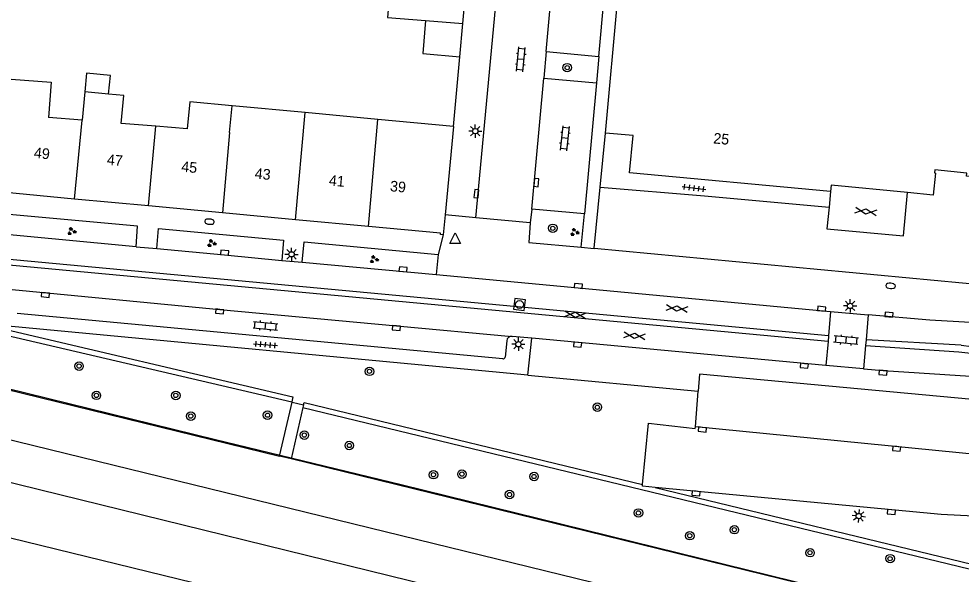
# Model space of a CAD drawing. Extents: x 132998 to 136004, y 396998 to 398512.
# Drawn here: x 133137.8 to 133226.6, y 397038.8 to 397091.2 of the extents above; entities that cross this region are included whole.
import ezdxf

# ---------------------------------------------------------------- set-up
doc = ezdxf.new("R2010")
doc.units = 0
for name, color, linetype in [('gg-afsc-muur', 7, 'Continuous'), ('gg-anno-huisnummerreeks BGT', 7, 'Continuous'), ('gg-aspt-spoorlijn', 7, 'Continuous'), ('gg-bbg-bijgebouw', 7, 'Continuous'), ('gg-bbg-gedigitaliseerde bebouwing', 7, 'Continuous'), ('gg-bbg-gedigitaliseerde bijgebouw', 7, 'Continuous'), ('gg-bbg-hoofdgebouw', 7, 'Continuous'), ('gg-bbg-luifel en loopbrug', 7, 'Continuous'), ('gg-bbg-tussenscheiding', 7, 'Continuous'), ('gg-knt-trap', 7, 'Continuous'), ('gg-knt-verharding', 7, 'Continuous'), ('gg-knt-verharding nz', 7, 'Continuous'), ('gg-kntw-beschoeiing', 7, 'Continuous'), ('gt-grn-groengrens', 7, 'Continuous'), ('gt-grn-weggrens', 7, 'Continuous'), ('gt-symb-boom', 7, 'Continuous'), ('gt-symb-brandkraan', 7, 'Continuous'), ('gt-symb-gesloten verharding', 7, 'Continuous'), ('gt-symb-groenvak', 7, 'Continuous'), ('gt-symb-klinker verharding', 7, 'Continuous'), ('gt-symb-kolk', 7, 'Continuous'), ('gt-symb-lichtmast', 7, 'Continuous'), ('gt-symb-rioolschacht', 7, 'Continuous'), ('gt-symb-tegel verharding', 7, 'Continuous'), ('gt-symb-waterafsluiter', 7, 'Continuous'), ('gx-grn-maaiveld', 7, 'Continuous')]:
    doc.layers.add(name, color=color, linetype=linetype)

# ---------------------------------------------------------------- blocks, each defined once
blk = doc.blocks.new('gt0-KOLK')
at = {"layer": 'gt-symb-kolk'}
blk.add_lwpolyline([(0, 0), (0.375, 0), (0.375, 0.4), (-0.375, 0.4), (-0.375, 0), (0, 0)], dxfattribs=at)
blk = doc.blocks.new('gt0-GESVH1')
at = {"layer": 'gt-symb-gesloten verharding'}
for p, q in [((-0.992, -0.261), (0.008, 0.239)), ((0.008, -0.261), (-0.992, 0.239)), ((0.008, 0.239), (1.008, -0.261)), ((1.008, 0.239), (0.008, -0.261))]:
    blk.add_line(p, q, dxfattribs=at)
blk = doc.blocks.new('gt0-BR')
at = {"layer": 'gt-symb-brandkraan'}
for centre, radius, start, end in [((-0.244, 0), 0.206, 107.56694, 252.43307), ((0.599, -2.664), 3, 106.89205, 107.56694), ((0, -0.691), 0.938, 73.10799, 106.89205), ((-0.599, -2.664), 3, 72.43309, 73.10799), ((0.244, 0), 0.206, 287.56695, 72.43309), ((0.599, 2.664), 3, 252.43307, 253.10797), ((0, 0.691), 0.938, 253.10797, 286.89206), ((-0.599, 2.664), 3, 286.89206, 287.56695)]:
    blk.add_arc(centre, radius, start, end, dxfattribs=at)
blk = doc.blocks.new('gt0-KL1')
at = {"layer": 'gt-symb-klinker verharding'}
for p, q in [((-1.15, 0.3), (1.15, 0.3)), ((-1, -0.3), (-1, 0.3)), ((-0.5, 0.3), (-0.5, 0.45)), ((0, -0.3), (0, 0.3)), ((0.5, 0.3), (0.5, 0.45)), ((1, -0.3), (1, 0.3)), ((-1.15, -0.3), (1.15, -0.3)), ((-0.5, -0.45), (-0.5, -0.3)), ((0.5, -0.45), (0.5, -0.3))]:
    blk.add_line(p, q, dxfattribs=at)
blk = doc.blocks.new('gt0-LMAST')
at = {"layer": 'gt-symb-lichtmast'}
for p, q in [((-0.182, 0.173), (-0.447, 0.438)), ((-0.005, 0.246), (-0.005, 0.621)), ((0.172, 0.173), (0.437, 0.438)), ((-0.255, -0.004), (-0.63, -0.004)), ((-0.182, -0.181), (-0.447, -0.446)), ((-0.005, -0.254), (-0.005, -0.629)), ((0.437, -0.446), (0.172, -0.181)), ((0.245, -0.004), (0.62, -0.004))]:
    blk.add_line(p, q, dxfattribs=at)
blk.add_circle((-0.005, -0.004), 0.25, dxfattribs=at)
blk = doc.blocks.new('gt0-WAFSL')
at = {"layer": 'gt-symb-waterafsluiter'}
for p, q in [((-0.5, -0.333), (0, 0.667)), ((0, 0.667), (0.5, -0.333)), ((0.5, -0.333), (-0.5, -0.333))]:
    blk.add_line(p, q, dxfattribs=at)
blk = doc.blocks.new('gt0-BOOM')
at = {"layer": 'gt-symb-boom'}
for radius in [0.4, 0.2]:
    blk.add_circle((0, 0), radius, dxfattribs=at)
blk = doc.blocks.new('gt0-GRVAK')
at = {"layer": 'gt-symb-groenvak'}
for p, q in [((-0.11, 0.189), (-0.228, 0.24)), ((-0.182, 0.153), (0.088, 0.153)), ((-0.091, 0.211), (-0.156, 0.322)), ((-0.047, 0.214), (-0.047, 0.393)), ((-0.004, 0.211), (0.061, 0.322)), ((0.015, 0.189), (0.133, 0.24)), ((0.262, -0.052), (0.197, 0.059)), ((0.305, -0.049), (0.305, 0.13)), ((0.349, -0.052), (0.414, 0.059)), ((-0.245, -0.228), (-0.363, -0.177)), ((-0.318, -0.264), (-0.047, -0.264)), ((-0.226, -0.206), (-0.291, -0.095)), ((-0.183, -0.203), (-0.183, -0.024)), ((-0.139, -0.206), (-0.074, -0.095)), ((-0.12, -0.228), (-0.002, -0.177)), ((0.243, -0.074), (0.125, -0.023)), ((0.17, -0.11), (0.441, -0.11)), ((0.368, -0.074), (0.486, -0.023))]:
    blk.add_line(p, q, dxfattribs=at)
blk = doc.blocks.new('gt0-TEG1')
at = {"layer": 'gt-symb-tegel verharding'}
for p, q in [((-1.125, 0), (1.125, 0)), ((-0.9, -0.25), (-0.9, 0.25)), ((-0.45, -0.25), (-0.45, 0.25)), ((0, -0.25), (0, 0.25)), ((0.45, -0.25), (0.45, 0.25)), ((0.9, -0.25), (0.9, 0.25))]:
    blk.add_line(p, q, dxfattribs=at)
blk = doc.blocks.new('gt0-RS')
at = {"layer": 'gt-symb-rioolschacht'}
blk.add_lwpolyline([(-0.5, -0.5), (0.5, -0.5), (0.5, 0.5), (-0.5, 0.5)], close=True, dxfattribs=at)
blk.add_circle((0, 0), 0.375, dxfattribs=at)

msp = doc.modelspace()

# ---------------------------------------------------------------- linework, layer by layer
at = {"layer": 'gg-afsc-muur'}
for p, q in [((133178.77, 397081), (133179.359, 397087.567)), ((133163.478, 397049.706), (133162.377, 397049.975)), ((133163.478, 397049.706), (133162.377, 397049.975)), ((133293.74, 397017.818), (133163.478, 397049.706)), ((133293.74, 397017.818), (133163.478, 397049.706))]:
    msp.add_line(p, q, dxfattribs=at)
at = {"layer": 'gg-aspt-spoorlijn'}
msp.add_line((133000, 397081.027), (133298.474, 397007.929), dxfattribs=at)
for points in [[(133000, 397085.097), (133023.788, 397079.291), (133131.609, 397052.829), (133298.931, 397011.894)], [(133000, 397075.839), (133096.746, 397052.101), (133297.901, 397002.954)]]:
    msp.add_lwpolyline(points, dxfattribs=at)
at = {"layer": 'gg-bbg-bijgebouw'}
msp.add_line((133179.643, 397090.725), (133179.919, 397093.721), dxfattribs=at)
at = {"layer": 'gg-bbg-gedigitaliseerde bebouwing'}
for p, q in [((133140.841, 397085.19), (133140.575, 397081.876)), ((133144.011, 397084.267), (133143.763, 397081.611)), ((133146.252, 397084.058), (133144.011, 397084.267)), ((133164.779, 397082.32), (133157.896, 397082.97)), ((133171.649, 397081.672), (133164.779, 397082.32)), ((133143.763, 397081.611), (133140.575, 397081.876)), ((133150.698, 397081.034), (133147.45, 397081.304)), ((133178.77, 397081), (133171.649, 397081.672)), ((133153.675, 397080.786), (133150.698, 397081.034))]:
    msp.add_line(p, q, dxfattribs=at)
for points in [[(133147.45, 397081.304), (133147.695, 397083.923), (133146.252, 397084.058)], [(133157.896, 397082.97), (133153.913, 397083.342), (133153.675, 397080.786)]]:
    msp.add_lwpolyline(points, dxfattribs=at)
at = {"layer": 'gg-bbg-gedigitaliseerde bijgebouw'}
msp.add_line((133176.146, 397091.006), (133179.643, 397090.725), dxfattribs=at)
msp.add_lwpolyline([(133172.805, 397094.266), (133172.549, 397091.296), (133176.146, 397091.006)], dxfattribs=at)
at = {"layer": 'gg-bbg-hoofdgebouw'}
for p, q in [((133193.09, 397080.4), (133194.795, 397098.793)), ((133137.08, 397085.49), (133140.841, 397085.19)), ((133178.77, 397081), (133177.98, 397072.698)), ((133143.043, 397074.185), (133136.251, 397074.82)), ((133150.023, 397073.533), (133143.043, 397074.185)), ((133156.983, 397072.883), (133150.023, 397073.533)), ((133163.879, 397072.238), (133156.983, 397072.883)), ((133177.98, 397072.698), (133177.8, 397070.81)), ((133170.751, 397071.596), (133163.879, 397072.238))]:
    msp.add_line(p, q, dxfattribs=at)
for points in [[(133214.33, 397074.88), (133195.38, 397076.64), (133195.7, 397080.16), (133193.09, 397080.4)], [(133233.58, 397075.72), (133227.141, 397076.348), (133227.168, 397076.627), (133224.148, 397076.921), (133224.121, 397076.642), (133224.211, 397076.633), (133224.009, 397074.56), (133221.575, 397074.797)], [(133221.575, 397074.797), (133214.39, 397075.498), (133214.33, 397074.88)], [(133177.8, 397070.81), (133177.54, 397070.85), (133177.56, 397070.96), (133170.751, 397071.596)]]:
    msp.add_lwpolyline(points, dxfattribs=at)
at = {"layer": 'gg-bbg-luifel en loopbrug'}
msp.add_line((133179.359, 397087.567), (133179.643, 397090.725), dxfattribs=at)
for points in [[(133176.146, 397091.006), (133175.865, 397087.88), (133179.359, 397087.567)], [(133146.252, 397084.058), (133146.418, 397085.833), (133144.177, 397086.042), (133144.011, 397084.267)]]:
    msp.add_lwpolyline(points, dxfattribs=at)
at = {"layer": 'gg-bbg-tussenscheiding'}
for p, q in [((133157.668, 397080.454), (133157.896, 397082.97)), ((133163.879, 397072.238), (133164.779, 397082.32)), ((133143.043, 397074.185), (133143.763, 397081.611)), ((133170.751, 397071.596), (133171.649, 397081.672)), ((133150.023, 397073.533), (133150.698, 397081.034)), ((133157.668, 397080.454), (133156.983, 397072.883))]:
    msp.add_line(p, q, dxfattribs=at)
at = {"layer": 'gg-knt-trap'}
for p, q in [((133214.33, 397074.88), (133214.181, 397073.41)), ((133162.377, 397049.975), (133163.477, 397054.631)), ((133163.477, 397054.631), (133163.574, 397055.041)), ((133163.574, 397055.041), (133164.628, 397054.78)), ((133164.628, 397054.78), (133164.573, 397054.536)), ((133164.573, 397054.536), (133163.478, 397049.706))]:
    msp.add_line(p, q, dxfattribs=at)
msp.add_lwpolyline([(133214.181, 397073.41), (133213.976, 397071.385), (133221.205, 397070.728), (133221.575, 397074.797)], dxfattribs=at)
at = {"layer": 'gg-knt-verharding'}
for p, q in [((133180.888, 397072.421), (133183.8, 397103.83)), ((133192.487, 397087.621), (133193.481, 397098.903)), ((133187.51, 397088.071), (133187.277, 397085.582)), ((133187.51, 397088.071), (133192.487, 397087.621)), ((133187.277, 397085.582), (133192.239, 397085.131)), ((133192.239, 397085.131), (133191.113, 397072.778)), ((133192.596, 397075.291), (133193.09, 397080.4)), ((133192.043, 397069.557), (133192.596, 397075.291)), ((133192.596, 397075.291), (133202.43, 397074.478)), ((133202.43, 397074.478), (133214.181, 397073.41)), ((133186.011, 397071.946), (133180.888, 397072.421)), ((133186.149, 397073.231), (133186.011, 397071.946)), ((133191.113, 397072.778), (133186.149, 397073.231)), ((133148.859, 397069.679), (133150.804, 397069.51)), ((133177.317, 397068.957), (133177.134, 397067.06)), ((133162.572, 397068.403), (133164.507, 397068.233)), ((133164.507, 397068.233), (133177.134, 397067.06)), ((133177.134, 397067.06), (133214.326, 397063.573)), ((133214.326, 397063.573), (133214.126, 397061.302)), ((133214.326, 397063.573), (133217.868, 397063.267)), ((133183.413, 397059.125), (133137.626, 397063.393)), ((133217.868, 397063.267), (133217.667, 397060.921)), ((133185.776, 397057.595), (133134.977, 397062.367)), ((133183.785, 397060.823), (133183.627, 397059.297)), ((133186.148, 397061.069), (133184.287, 397061.244)), ((133185.776, 397057.595), (133186.148, 397061.069)), ((133213.879, 397058.486), (133186.148, 397061.069)), ((133214.126, 397061.302), (133214.08, 397060.772)), ((133217.667, 397060.921), (133217.622, 397060.394)), ((133226.633, 397060.413), (133217.667, 397060.921)), ((133214.08, 397060.772), (133213.879, 397058.486)), ((133217.622, 397060.394), (133217.432, 397058.174)), ((133217.622, 397060.394), (133226.414, 397059.782)), ((133217.432, 397058.174), (133213.879, 397058.486)), ((133217.432, 397058.174), (133219.287, 397058.019)), ((133219.287, 397058.019), (133228.484, 397057.43)), ((133201.58, 397052.738), (133201.842, 397056.086))]:
    msp.add_line(p, q, dxfattribs=at)
for points in [[(133148.859, 397069.679), (133148.993, 397071.615), (133136.203, 397072.795)], [(133186.011, 397071.946), (133185.863, 397070.102), (133190.823, 397069.643)], [(133148.859, 397069.679), (133137.248, 397070.793), (133136.073, 397070.882)], [(133150.804, 397069.51), (133150.955, 397071.42), (133162.749, 397070.311), (133162.572, 397068.403)], [(133164.507, 397068.233), (133164.699, 397070.145), (133177.317, 397068.957)], [(133192.043, 397069.557), (133232.1, 397065.79), (133242.55, 397070.43)], [(133150.804, 397069.51), (133157.185, 397068.93), (133162.572, 397068.403)], [(133190.823, 397069.643), (133192.04, 397069.531), (133192.043, 397069.557)], [(133214.08, 397060.772), (133136.179, 397068.014), (133135.632, 397068.061)], [(133214.126, 397061.302), (133136.243, 397068.553), (133135.715, 397068.593)], [(133137.156, 397065.651), (133156.738, 397063.791), (133173.408, 397062.236), (133184.287, 397061.244)], [(133229.16, 397062.468), (133223.69, 397062.769), (133217.868, 397063.267)], [(133237.59, 397055.191), (133237.36, 397055.09), (133230.74, 397055), (133201.968, 397057.692), (133201.842, 397056.086)], [(133196.606, 397047.301), (133197.16, 397053.07), (133201.567, 397052.566), (133201.58, 397052.738)], [(133197.779, 397047.017), (133196.59, 397047.13), (133196.606, 397047.301)], [(133231.483, 397044.133), (133224.75, 397044.46), (133197.779, 397047.017)]]:
    msp.add_lwpolyline(points, dxfattribs=at)
for centre, radius, start, end in [((133230.067, 397085.427), 25.249, 262.18313, 297.37096), ((133184.25, 397060.779), 0.467, 85.42767, 174.54178), ((133229.546, 397086.551), 26.951, 263.32581, 292.38921), ((133183.411, 397059.347), 0.222, 270.62746, 346.95289)]:
    msp.add_arc(centre, radius, start, end, dxfattribs=at)
at = {"layer": 'gg-knt-verharding nz'}
for p, q in [((133186.149, 397073.231), (133187.277, 397085.582)), ((133230.616, 397049.869), (133201.58, 397052.738))]:
    msp.add_line(p, q, dxfattribs=at)
msp.add_lwpolyline([(133187.51, 397088.071), (133187.881, 397092.238), (133188.132, 397094.871), (133188.621, 397100.501)], dxfattribs=at)
at = {"layer": 'gg-kntw-beschoeiing'}
msp.add_lwpolyline([(133293.908, 397017.321), (133294.015, 397017.844), (133281.102, 397020.96), (133261.323, 397025.845), (133257.889, 397026.669), (133240.574, 397030.918), (133215.176, 397037.087), (133173.826, 397047.249), (133156.339, 397051.485), (133065.484, 397073.822), (133055.258, 397076.278), (133002.984, 397089.089), (133000, 397089.82)], dxfattribs=at)
at = {"layer": 'gt-grn-groengrens'}
for p, q in [((133192.487, 397087.621), (133192.239, 397085.131)), ((133190.823, 397069.643), (133191.113, 397072.778)), ((133185.776, 397057.595), (133201.842, 397056.086)), ((133163.517, 397055.064), (133163.574, 397055.041)), ((133197.779, 397047.017), (133231.465, 397038.868))]:
    msp.add_line(p, q, dxfattribs=at)
for points in [[(133041.069, 397084.222), (133093.229, 397072.243), (133093.148, 397070.541), (133113.163, 397066.046), (133113.393, 397066.97), (133134.695, 397061.803), (133163.517, 397055.064)], [(133134.951, 397062.257), (133163.631, 397055.55), (133163.517, 397055.064)], [(133164.628, 397054.78), (133164.687, 397055.023), (133196.606, 397047.301)], [(133164.573, 397054.536), (133272.285, 397028.478), (133272.447, 397029.147)]]:
    msp.add_lwpolyline(points, dxfattribs=at)
at = {"layer": 'gt-grn-weggrens'}
for p, q in [((133180.888, 397072.421), (133177.98, 397072.698)), ((133177.8, 397070.81), (133177.317, 397068.957))]:
    msp.add_line(p, q, dxfattribs=at)
at = {"layer": 'gx-grn-maaiveld'}
msp.add_lwpolyline([(133004.183, 397088.7), (133026.835, 397083.155), (133162.377, 397049.975)], dxfattribs=at)

# ---------------------------------------------------------------- block references
at = {"layer": 'gt-symb-boom'}
for p in [(133189.489, 397086.558), (133188.133, 397071.424), (133143.471, 397058.443), (133170.848, 397057.95), (133145.105, 397055.686), (133152.592, 397055.679), (133192.333, 397054.57), (133154.001, 397053.734), (133161.237, 397053.819), (133164.709, 397051.945), (133168.948, 397050.964), (133176.883, 397048.21), (133179.568, 397048.27), (133186.363, 397048.041), (133184.055, 397046.342), (133196.208, 397044.612), (133205.25, 397043.031), (133201.048, 397042.464), (133212.386, 397040.867), (133219.934, 397040.307)]:
    msp.add_blockref('gt0-BOOM', p, dxfattribs=at)
at = {"layer": 'gt-symb-brandkraan'}
for p, rotation in [((133155.763, 397072.051), 174.3179150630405), ((133219.982, 397066.002), 176.0449623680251)]:
    msp.add_blockref('gt0-BR', p, dxfattribs=dict(at, rotation=rotation))
at = {"layer": 'gt-symb-gesloten verharding'}
for p, rotation in [((133217.641, 397073.027), -7.416577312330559), ((133190.245, 397063.276), -5.391463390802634), ((133199.823, 397063.881), -5.391463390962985), ((133195.831, 397061.307), -5.391463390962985)]:
    msp.add_blockref('gt0-GESVH1', p, dxfattribs=dict(at, rotation=rotation))
at = {"layer": 'gt-symb-groenvak'}
for p in [(133142.759, 397071.133), (133190.177, 397071.058), (133155.957, 397070.011), (133171.266, 397068.494)]:
    msp.add_blockref('gt0-GRVAK', p, dxfattribs=at)
at = {"layer": 'gt-symb-klinker verharding'}
for p, rotation in [((133185.114, 397087.339), 84.72259391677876), ((133189.272, 397079.908), 83.79902900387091), ((133161.046, 397062.234), -5.049166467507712), ((133215.771, 397060.88), 174.4890230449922)]:
    msp.add_blockref('gt0-KL1', p, dxfattribs=dict(at, rotation=rotation))
at = {"layer": 'gt-symb-kolk'}
for p, rotation in [((133186.375, 397075.756), -95.04916646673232), ((133181.131, 397074.663), 84.03296237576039), ((133157.185, 397068.93), -5.2203616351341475), ((133174.003, 397067.358), -5.2774060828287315), ((133190.529, 397065.802), -5.391463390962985), ((133140.313, 397065.351), 174.5460811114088), ((133156.738, 397063.791), 174.66555996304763), ((133213.46, 397063.648), -5.391463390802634), ((133219.818, 397063.099), -3.669254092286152), ((133173.408, 397062.236), 174.77963836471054), ((133190.485, 397060.66), 174.6655599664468), ((133211.856, 397058.672), 174.77963835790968), ((133219.287, 397058.019), 175.24111432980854), ((133202.244, 397052.671), 174.26090150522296), ((133220.563, 397050.861), 174.14690870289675), ((133201.647, 397046.649), 174.60853661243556), ((133220.065, 397044.904), 174.60853660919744)]:
    msp.add_blockref('gt0-KOLK', p, dxfattribs=dict(at, rotation=rotation))
at = {"layer": 'gt-symb-lichtmast'}
for p in [(133180.832, 397080.578), (133163.515, 397068.977), (133216.164, 397064.113), (133184.892, 397060.508)]:
    msp.add_blockref('gt0-LMAST', p, dxfattribs=at)
at = {"layer": 'gt-symb-lichtmast', "rotation": -5.391463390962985}
msp.add_blockref('gt0-LMAST', (133216.986, 397044.322), dxfattribs=at)
at = {"layer": 'gt-symb-rioolschacht', "rotation": 172.00768607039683}
msp.add_blockref('gt0-RS', (133184.994, 397064.248), dxfattribs=at)
at = {"layer": 'gt-symb-tegel verharding'}
for p, rotation in [((133201.455, 397075.218), -7.352379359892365), ((133161.049, 397060.465), -4.701808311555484)]:
    msp.add_blockref('gt0-TEG1', p, dxfattribs=dict(at, rotation=rotation))
at = {"layer": 'gt-symb-waterafsluiter'}
msp.add_blockref('gt0-WAFSL', (133178.921, 397070.329), dxfattribs=at)

# ---------------------------------------------------------------- texts
at = {"layer": 'gg-anno-huisnummerreeks BGT'}
for s, p in [('25', (133203.233, 397079.426)), ('49', (133139.182, 397078.061)), ('47', (133146.063, 397077.418)), ('45', (133153.074, 397076.763)), ('43', (133160.002, 397076.115)), ('41', (133166.992, 397075.462)), ('39', (133172.755, 397074.924))]:
    msp.add_text(s, height=1, rotation=354.7, dxfattribs=at).set_placement(p)

doc.saveas('drawing.dxf')
